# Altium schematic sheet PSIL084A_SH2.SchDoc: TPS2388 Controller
size 558 x 431 mm; Date: Not shown in title block; ApprovedBy: Not shown in title block; CheckedBy: Not shown in title block; Author: Not shown in title block; CompanyName: Not shown in title block; DrawnBy: D Strasser; Engineer: Not shown in title block; Organization: Not shown in title block; Address1: Not shown in title block; Address2: Not shown in title block; Address3: Not shown in title block; Address4: Not shown in title block; DocumentNumber: 2; Revision: Use project parameter SCH_Rev; SheetNumber: 2; SheetTotal: 3; PageSetup: Record=PageOptions¦CenterHorizontal=True¦CenterVertical=True¦PrintScale=1.00¦XCorrection=1.00¦YCorrection=1.00¦PrintKind=0¦BorderSize=5000000¦LeftOffset=0¦BottomOffset=0¦Orientation=2¦PaperLength=1000¦PaperWidth=1000¦Scale=100¦PaperSource=15¦PrintQuality=600¦MediaType=1¦DitherType=10¦PaperKind=Letter¦PrintScaleMode=1
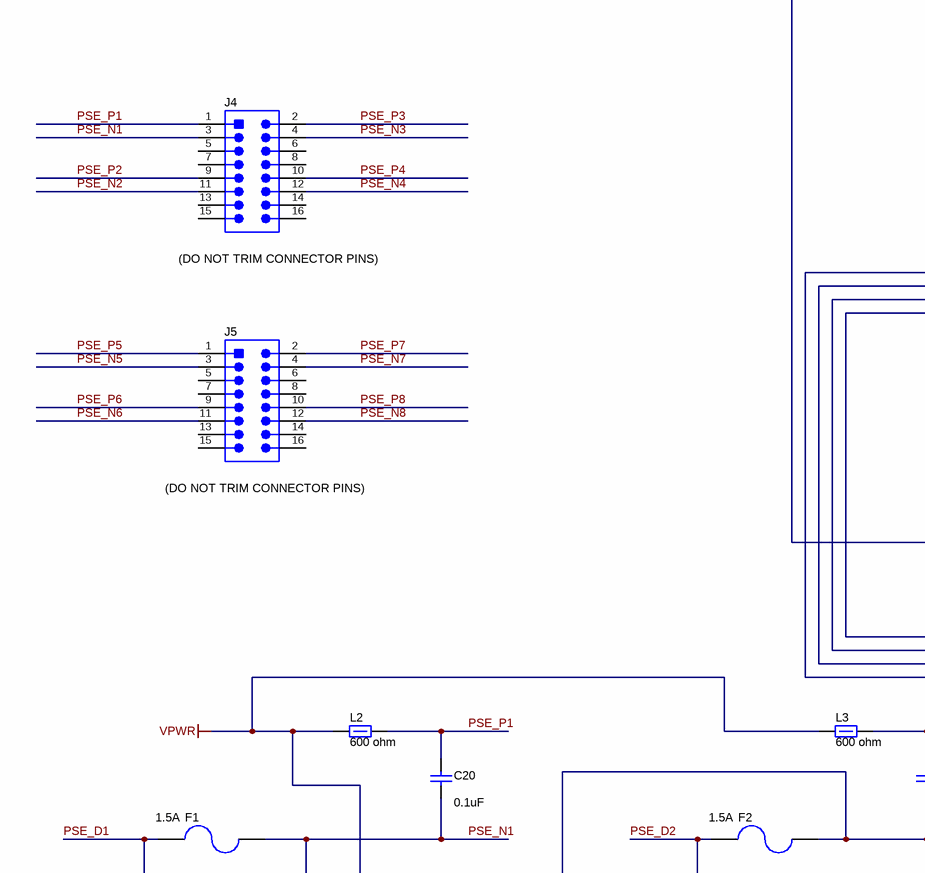
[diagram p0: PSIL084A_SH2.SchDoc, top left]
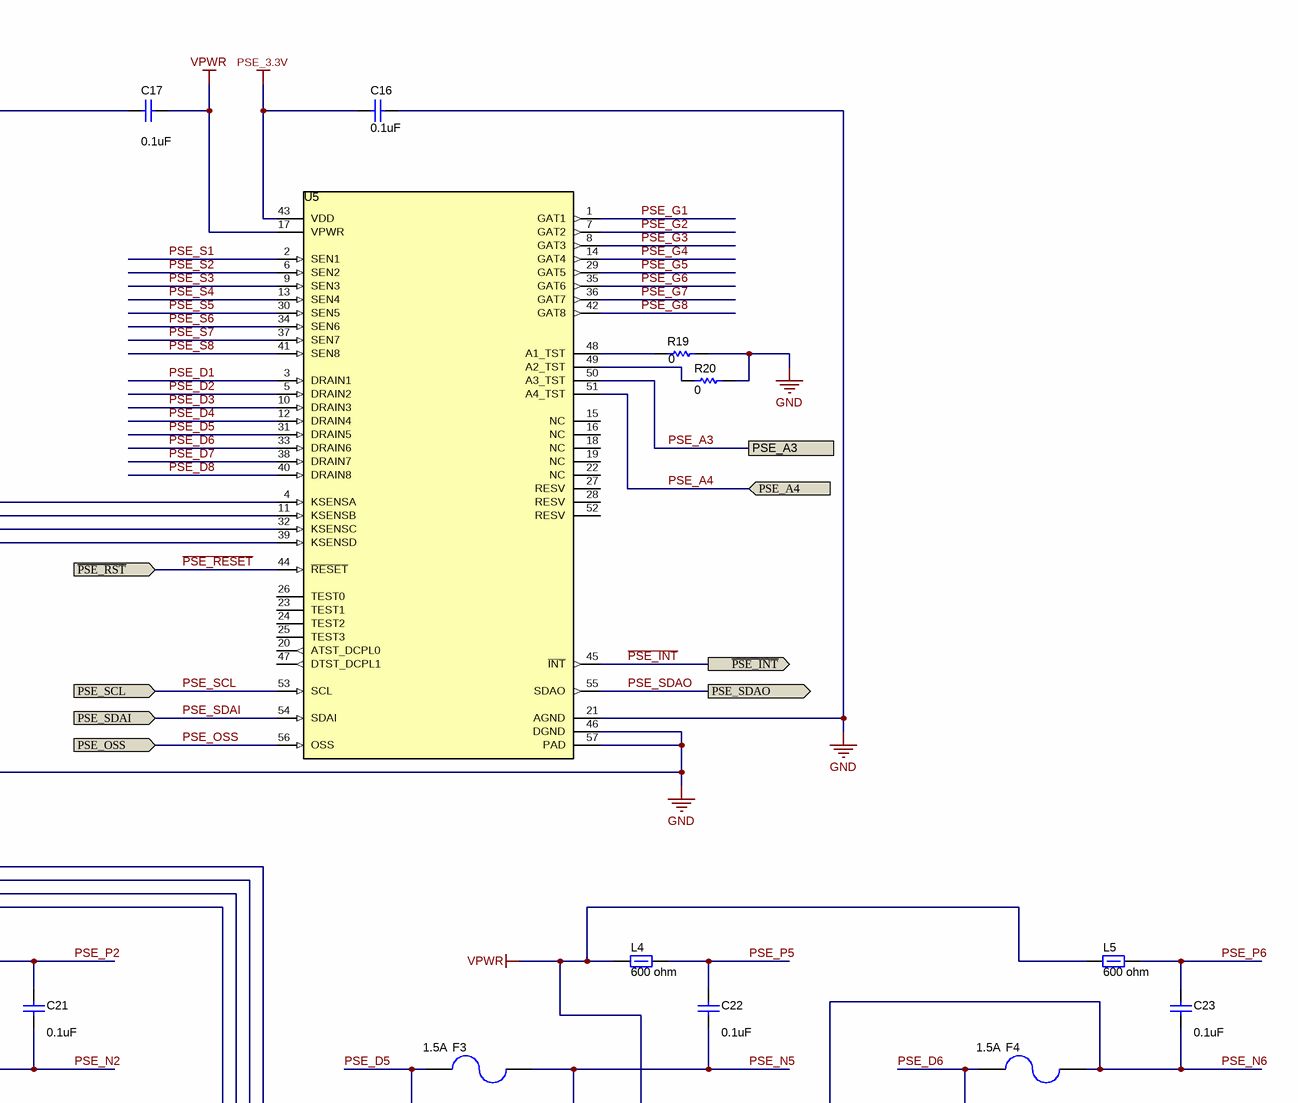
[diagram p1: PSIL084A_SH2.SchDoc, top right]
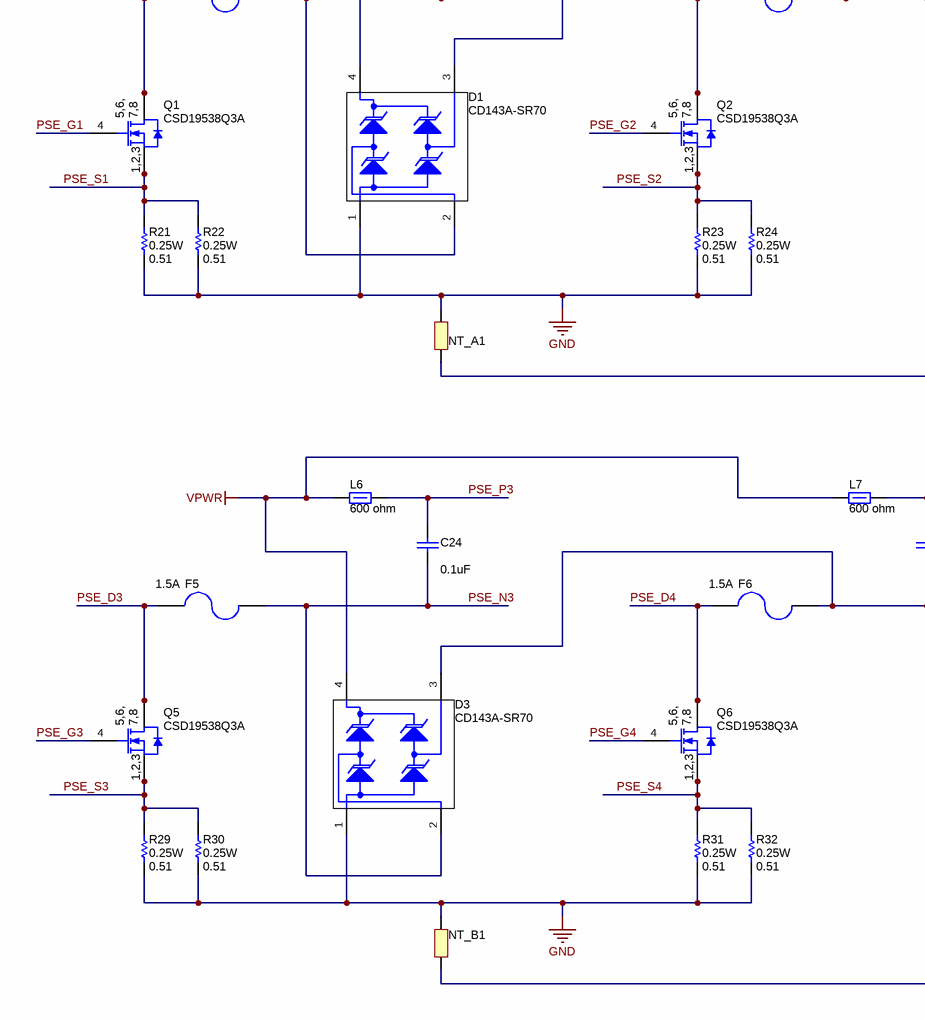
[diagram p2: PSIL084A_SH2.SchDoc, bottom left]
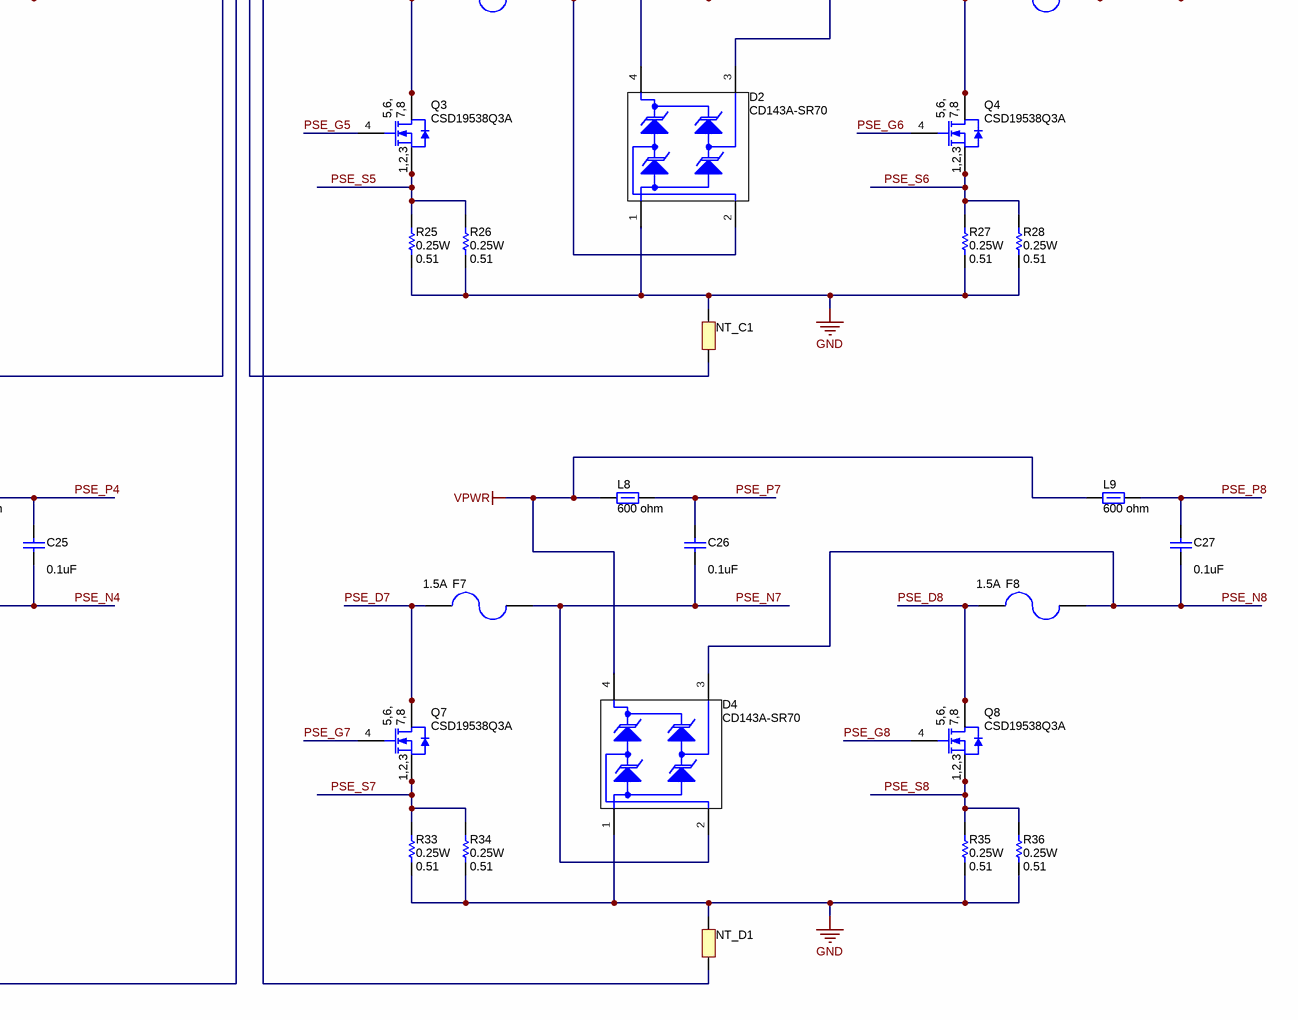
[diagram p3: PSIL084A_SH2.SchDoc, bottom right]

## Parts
C16  ValueDisplayed: 0.1uF  [0603]  (hidden comment: 885012206095)
C17  ValueDisplayed: 0.1uF  [0805_HV]  (hidden comment: C2012X7R2A104K125AA)
C20  ValueDisplayed: 0.1uF  [0805_HV]  (hidden comment: C2012X7R2A104K125AA)
C21  ValueDisplayed: 0.1uF  [0805_HV]  (hidden comment: C2012X7R2A104K125AA)
C22  ValueDisplayed: 0.1uF  [0805_HV]  (hidden comment: C2012X7R2A104K125AA)
C23  ValueDisplayed: 0.1uF  [0805_HV]  (hidden comment: C2012X7R2A104K125AA)
C24  ValueDisplayed: 0.1uF  [0805_HV]  (hidden comment: C2012X7R2A104K125AA)
C25  ValueDisplayed: 0.1uF  [0805_HV]  (hidden comment: C2012X7R2A104K125AA)
C26  ValueDisplayed: 0.1uF  [0805_HV]  (hidden comment: C2012X7R2A104K125AA)
C27  ValueDisplayed: 0.1uF  [0805_HV]  (hidden comment: C2012X7R2A104K125AA)
D1  CD143A-SR70  [SOT-143-4]
D2  CD143A-SR70  [SOT-143-4]
D3  CD143A-SR70  [SOT-143-4]
D4  CD143A-SR70  [SOT-143-4]
F1  Irating_A: 1.5A  [1206]  (hidden comment: C1S 1.5)
F2  Irating_A: 1.5A  [1206]  (hidden comment: C1S 1.5)
F3  Irating_A: 1.5A  [1206]  (hidden comment: C1S 1.5)
F4  Irating_A: 1.5A  [1206]  (hidden comment: C1S 1.5)
F5  Irating_A: 1.5A  [1206]  (hidden comment: C1S 1.5)
F6  Irating_A: 1.5A  [1206]  (hidden comment: C1S 1.5)
F7  Irating_A: 1.5A  [1206]  (hidden comment: C1S 1.5)
F8  Irating_A: 1.5A  [1206]  (hidden comment: C1S 1.5)
J4  TSW-108-09-G-D  [TSW-108-07-G-D]  (value not drawn)
J5  TSW-108-09-G-D  [TSW-108-07-G-D]  (value not drawn)
L2  ValueDisplayed: 600 ohm  [0603]  (hidden comment: MPZ1608S601ATD25)
L3  ValueDisplayed: 600 ohm  [0603]  (hidden comment: MPZ1608S601ATD25)
L4  ValueDisplayed: 600 ohm  [0603]  (hidden comment: MPZ1608S601ATD25)
L5  ValueDisplayed: 600 ohm  [0603]  (hidden comment: MPZ1608S601ATD25)
L6  ValueDisplayed: 600 ohm  [0603]  (hidden comment: MPZ1608S601ATD25)
L7  ValueDisplayed: 600 ohm  [0603]  (hidden comment: MPZ1608S601ATD25)
L8  ValueDisplayed: 600 ohm  [0603]  (hidden comment: MPZ1608S601ATD25)
L9  ValueDisplayed: 600 ohm  [0603]  (hidden comment: MPZ1608S601ATD25)
NT_A1  Net-Tie  [Net-Tie_10milWide_30milLong]  (value not drawn)  (net tie, no BOM)
NT_B1  Net-Tie  [Net-Tie_10milWide_30milLong]  (value not drawn)  (net tie, no BOM)
NT_C1  Net-Tie  [Net-Tie_10milWide_30milLong]  (value not drawn)  (net tie, no BOM)
NT_D1  Net-Tie  [Net-Tie_10milWide_30milLong]  (value not drawn)  (net tie, no BOM)
Q1  CSD19538Q3A  [DNH0008A_NV]
Q2  CSD19538Q3A  [DNH0008A_NV]
Q3  CSD19538Q3A  [DNH0008A_NV]
Q4  CSD19538Q3A  [DNH0008A_NV]
Q5  CSD19538Q3A  [DNH0008A_NV]
Q6  CSD19538Q3A  [DNH0008A_NV]
Q7  CSD19538Q3A  [DNH0008A_NV]
Q8  CSD19538Q3A  [DNH0008A_NV]
R19  ValueDisplayed: 0  [0402]  (hidden comment: ERJ-2GE0R00X)
R20  ValueDisplayed: 0  [0402]  (hidden comment: ERJ-2GE0R00X)
R21  Value2: 0.25W  ValueDisplayed: 0.51  [0805L]  (hidden comment: CRM0805-FX-R510ELF)
R22  Value2: 0.25W  ValueDisplayed: 0.51  [0805L]  (hidden comment: CRM0805-FX-R510ELF)
R23  Value2: 0.25W  ValueDisplayed: 0.51  [0805L]  (hidden comment: CRM0805-FX-R510ELF)
R24  Value2: 0.25W  ValueDisplayed: 0.51  [0805L]  (hidden comment: CRM0805-FX-R510ELF)
R25  Value2: 0.25W  ValueDisplayed: 0.51  [0805L]  (hidden comment: CRM0805-FX-R510ELF)
R26  Value2: 0.25W  ValueDisplayed: 0.51  [0805L]  (hidden comment: CRM0805-FX-R510ELF)
R27  Value2: 0.25W  ValueDisplayed: 0.51  [0805L]  (hidden comment: CRM0805-FX-R510ELF)
R28  Value2: 0.25W  ValueDisplayed: 0.51  [0805L]  (hidden comment: CRM0805-FX-R510ELF)
R29  Value2: 0.25W  ValueDisplayed: 0.51  [0805L]  (hidden comment: CRM0805-FX-R510ELF)
R30  Value2: 0.25W  ValueDisplayed: 0.51  [0805L]  (hidden comment: CRM0805-FX-R510ELF)
R31  Value2: 0.25W  ValueDisplayed: 0.51  [0805L]  (hidden comment: CRM0805-FX-R510ELF)
R32  Value2: 0.25W  ValueDisplayed: 0.51  [0805L]  (hidden comment: CRM0805-FX-R510ELF)
R33  Value2: 0.25W  ValueDisplayed: 0.51  [0805L]  (hidden comment: CRM0805-FX-R510ELF)
R34  Value2: 0.25W  ValueDisplayed: 0.51  [0805L]  (hidden comment: CRM0805-FX-R510ELF)
R35  Value2: 0.25W  ValueDisplayed: 0.51  [0805L]  (hidden comment: CRM0805-FX-R510ELF)
R36  Value2: 0.25W  ValueDisplayed: 0.51  [0805L]  (hidden comment: CRM0805-FX-R510ELF)
U5  TPS2388RTQR  [RTQ0056E]

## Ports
PSE_A3, PSE_A4 (in), PSE_OSS (in), PSE_SCL (in), PSE_SDAI (in), PSE_SDAO (out), ~{PSE_INT} (out), ~{PSE_RST} (in)

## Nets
GND: C16.2 C17.2 D1.1(A) D2.1(A) D3.1(A) D4.1(A) NT_A1.1 NT_B1.2 NT_C1.2 NT_D1.2 R19.2 R20.2 R21.2 R22.2 R23.2 R24.2 R25.2 R26.2 R27.2 R28.2 R29.2 R30.2 R31.2 R32.2 R33.2 R34.2 R35.2 R36.2 U5.21(AGND) U5.46(DGND) U5.57(PAD)
PSE_3.3V: C16.1 U5.43(VDD)
VPWR: C17.1 D1.4(K3) D2.4(K3) D3.4(K3) D4.4(K3) L2.1 L3.1 L4.1 L5.1 L6.1 L7.1 L8.1 L9.1 U5.17(VPWR)
~{PSE_INT}: U5.45(~{INT}) ; port ~{PSE_INT}
~{PSE_RESET}: U5.44(~{RESET}) ; port ~{PSE_RST}
PSE_A3: U5.50(A3_TST) ; port PSE_A3
PSE_A4: U5.51(A4_TST) ; port PSE_A4
PSE_D1: F1.2 Q1.5(D) Q1.6(D) Q1.7(D) Q1.8(D) Q1.9(D) U5.3(DRAIN1)
PSE_D2: F2.2 Q2.5(D) Q2.6(D) Q2.7(D) Q2.8(D) Q2.9(D) U5.5(DRAIN2)
PSE_D3: F5.2 Q5.5(D) Q5.6(D) Q5.7(D) Q5.8(D) Q5.9(D) U5.10(DRAIN3)
PSE_D4: F6.2 Q6.5(D) Q6.6(D) Q6.7(D) Q6.8(D) Q6.9(D) U5.12(DRAIN4)
PSE_D5: F3.2 Q3.5(D) Q3.6(D) Q3.7(D) Q3.8(D) Q3.9(D) U5.31(DRAIN5)
PSE_D6: F4.2 Q4.5(D) Q4.6(D) Q4.7(D) Q4.8(D) Q4.9(D) U5.33(DRAIN6)
PSE_D7: F7.2 Q7.5(D) Q7.6(D) Q7.7(D) Q7.8(D) Q7.9(D) U5.38(DRAIN7)
PSE_D8: F8.2 Q8.5(D) Q8.6(D) Q8.7(D) Q8.8(D) Q8.9(D) U5.40(DRAIN8)
PSE_G1: Q1.4(G) U5.1(GAT1)
PSE_G2: Q2.4(G) U5.7(GAT2)
PSE_G3: Q5.4(G) U5.8(GAT3)
PSE_G4: Q6.4(G) U5.14(GAT4)
PSE_G5: Q3.4(G) U5.29(GAT5)
PSE_G6: Q4.4(G) U5.35(GAT6)
PSE_G7: Q7.4(G) U5.36(GAT7)
PSE_G8: Q8.4(G) U5.42(GAT8)
PSE_N1: C20.2 D1.2(K1) F1.1 J4.3
PSE_N2: C21.2 D1.3(K2) F2.1 J4.11
PSE_N3: C24.2 D3.2(K1) F5.1 J4.4
PSE_N4: C25.2 D3.3(K2) F6.1 J4.12
PSE_N5: C22.2 D2.2(K1) F3.1 J5.3
PSE_N6: C23.2 D2.3(K2) F4.1 J5.11
PSE_N7: C26.2 D4.2(K1) F7.1 J5.4
PSE_N8: C27.2 D4.3(K2) F8.1 J5.12
PSE_OSS: U5.56(OSS) ; port PSE_OSS
PSE_P1: C20.1 J4.1 L2.2
PSE_P2: C21.1 J4.9 L3.2
PSE_P3: C24.1 J4.2 L6.2
PSE_P4: C25.1 J4.10 L7.2
PSE_P5: C22.1 J5.1 L4.2
PSE_P6: C23.1 J5.9 L5.2
PSE_P7: C26.1 J5.2 L8.2
PSE_P8: C27.1 J5.10 L9.2
PSE_S1: Q1.1(S) Q1.2(S) Q1.3(S) R21.1 R22.1 U5.2(SEN1)
PSE_S2: Q2.1(S) Q2.2(S) Q2.3(S) R23.1 R24.1 U5.6(SEN2)
PSE_S3: Q5.1(S) Q5.2(S) Q5.3(S) R29.1 R30.1 U5.9(SEN3)
PSE_S4: Q6.1(S) Q6.2(S) Q6.3(S) R31.1 R32.1 U5.13(SEN4)
PSE_S5: Q3.1(S) Q3.2(S) Q3.3(S) R25.1 R26.1 U5.30(SEN5)
PSE_S6: Q4.1(S) Q4.2(S) Q4.3(S) R27.1 R28.1 U5.34(SEN6)
PSE_S7: Q7.1(S) Q7.2(S) Q7.3(S) R33.1 R34.1 U5.37(SEN7)
PSE_S8: Q8.1(S) Q8.2(S) Q8.3(S) R35.1 R36.1 U5.41(SEN8)
PSE_SCL: U5.53(SCL) ; port PSE_SCL
PSE_SDAI: U5.54(SDAI) ; port PSE_SDAI
PSE_SDAO: U5.55(SDAO) ; port PSE_SDAO
NetNT_A1_2: NT_A1.2 U5.4(KSENSA)
NetNT_B1_1: NT_B1.1 U5.11(KSENSB)
NetNT_C1_1: NT_C1.1 U5.32(KSENSC)
NetNT_D1_1: NT_D1.1 U5.39(KSENSD)
NetR19_1: R19.1 U5.48(A1_TST)
NetR20_1: R20.1 U5.49(A2_TST)

Not connected (* = marked no-connect by the designer): J4 5 6 7 8 13 14 15 16; J5 5 6 7 8 13 14 15 16; U5 15(NC) 16(NC) 18(NC) 19(NC) 20(ATST_DCPL0) 22(NC) 23(TEST1) 24(TEST2) 25(TEST3) 26(TEST0) 27(RESV) 28(RESV) 47(DTST_DCPL1) 52(RESV)

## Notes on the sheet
- (near J4) (DO NOT TRIM CONNECTOR PINS)
- (near J5) (DO NOT TRIM CONNECTOR PINS)

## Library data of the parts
C16 = CMP-0006837-4: CAP, CERM, 0.1 uF, 50 V, +/- 10%, X7R, 0603; Manufacturer: Wurth Elektronik; TaMin_C: -55°C; Polarized: N; SizeAreaWB_mm2: 4.68; Value1: Unknown; U/M: EA; Value: 0.1uF; TaMax_C: 125°C; SizeZ_mm: 1; SizeX_mm: 1.6; SizeY_mm: 0.8; Value2: 50V; SizeArea_mm2: 1.28; CompType: Capacitor; Cap_F: 100nF; AEC Category: Q200
C17 C20-C27 = CMP-0007886-2: CAP, CERM, 0.1 uF, 100 V, +/- 10%, X7R, 0805; Manufacturer: TDK; TaMin_C: -55°C; ESR_ohm: 0.020726; Polarized: N; SizeAreaWB_mm2: 6.75; Value1: 0.020726 ohm; U/M: EA; Value: 0.1uF; TaMax_C: 125°C; SizeZ_mm: 1.45; SizeX_mm: 2; SizeY_mm: 1.25; Cap_Case: 0805; Value2: 100V; SizeArea_mm2: 2.5; CompType: Capacitor; Cap_F: 100nF; IRMS_A: 1.456A; AEC Category: Q200
D1-D4 = CMP-0002018-2: ESD Suppressor Diode Arrays, 7V, SMD; Manufacturer: Bourns; CompType: ESD Diode Array
F1-F8 = CMP-0003587-2: Fuse, 1.5 A, 63VAC/VDC, SMD; Manufacturer: Bel Fuse; SizeAreaWB_mm2: 10.92; VAC_V: 63V; SizeZ_mm: 1.35; SizeX_mm: 3.2; SizeY_mm: 1.6; SizeArea_mm2: 5.12; Rtyp_Ohm: 0.182; MeltingTyp: 0.27
J4 J5 = CMP-0075418-1: Header, 100mil, 8x2, Gold, TH; Manufacturer: Samtec; Pitch_mm: 2.54; Cert_VDE: N; Gender: Male; Cert_CSA: Y; Voltage_V: 550V; Green_REACh: Passed; Current_A: 6.3A; CT: False; Green_Lifecycle: Active; Row_Count: 2; CNHeader: True
L2-L9 = CMP-0078795-1: Ferrite Bead, 600 ohm @ 100 MHz, 1 A, 0603; Manufacturer: TDK; ZTyp@100MHz_Ohm: 600; SizeAreaWB_mm2: 4.68; DCR_ohm: 1.5d; Value1: 0.15 ohm; Value: 600 ohm; Imax_A: 1A; SizeZ_mm: 1; SizeX_mm: 1.6; SizeY_mm: 0.8; SizeArea_mm2: 1.28
NT_A1 NT_B1 NT_C1 NT_D1 = CMP-0078142-2: Single point connection between nets.
Q1 = CMP-0000969-3: MOSFET, N-CH, 100 V, 5 A, DNH0008A (VSONP-8); Alternate Manufacturer: None; Manufacturer: Texas Instruments; SizeZ_mm: 0.9; ChType: N; VdsMax_V: 100V; SizeX_mm: 3.3; SizeAreaWB_mm2: 18.49; Vgs_V: 20V; Value: 100V; SizeArea_mm2: 10.89; AEC Category: Q101; IdsMax_A: 5A; Value2: 7.2 nC; QgTyp_nC: 7.2; ChMode: Enhancement
Q2-Q8 = CMP-0000969-3: MOSFET, N-CH, 100 V, 5 A, DNH0008A (VSONP-8); Alternate Manufacturer: None; Manufacturer: Texas Instruments; SizeZ_mm: 0.9; ChType: N; Value2: 7.2 nC; VdsMax_V: 100V; SizeX_mm: 3.3; SizeAreaWB_mm2: 18.49; Vgs_V: 20V; QgTyp_nC: 7.2; Value: 100V; SizeArea_mm2: 10.89; AEC Category: Q101; IdsMax_A: 5A; ChMode: Enhancement
R19 R20 = CMP-0026992-3: RES, 0, 5%, 0.1 W, AEC-Q200 Grade 0, 0402; Manufacturer: Panasonic; Power_W: 100mW; TempCo: 600 ppm/C; Value_Code: 0000; Value: 0; EIA_Code: E24; SizeX_mm: 1; SizeY_mm: 0.5; SizeZ_mm: 0.6; Value2: 0.1W; AEC Qualified: Y; VDC_V: 50V; AEC Category: Q200; SizeAreaWB_mm2: 3
R21-R36 = CMP-0021516-2: RES, 0.51, 1%, 0.25 W, 0805; Manufacturer: Bourns; Power_W: 250mW; TempCo: 100 ppm/C; Value_Code: R510; U/M: EA; Value: 0.51; EIA_Code: E96; Res_ohm: 5.1d; SizeX_mm: 2; SizeY_mm: 1.25; SizeZ_mm: 1.45; SizeArea_mm2: 2.5; CompType: Resistor; VDC_V: 0V; AEC Category: Q200
U5 = CMP-0014018-5: IEEE 802.3at 8-Port Power-over-Ethernet PSE, RTQ0056E (VQFN-56); Manufacturer: Texas Instruments; Alternate PartNumber: TPS2388RTQT; SizeX_mm: 8.0; CompType: IC; SizeZ_mm: 1.0; SizeArea_mm2: 64.0; SizeAreaWB_mm2: 100.0; AEC Category: Q200; AEC Qualified: N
